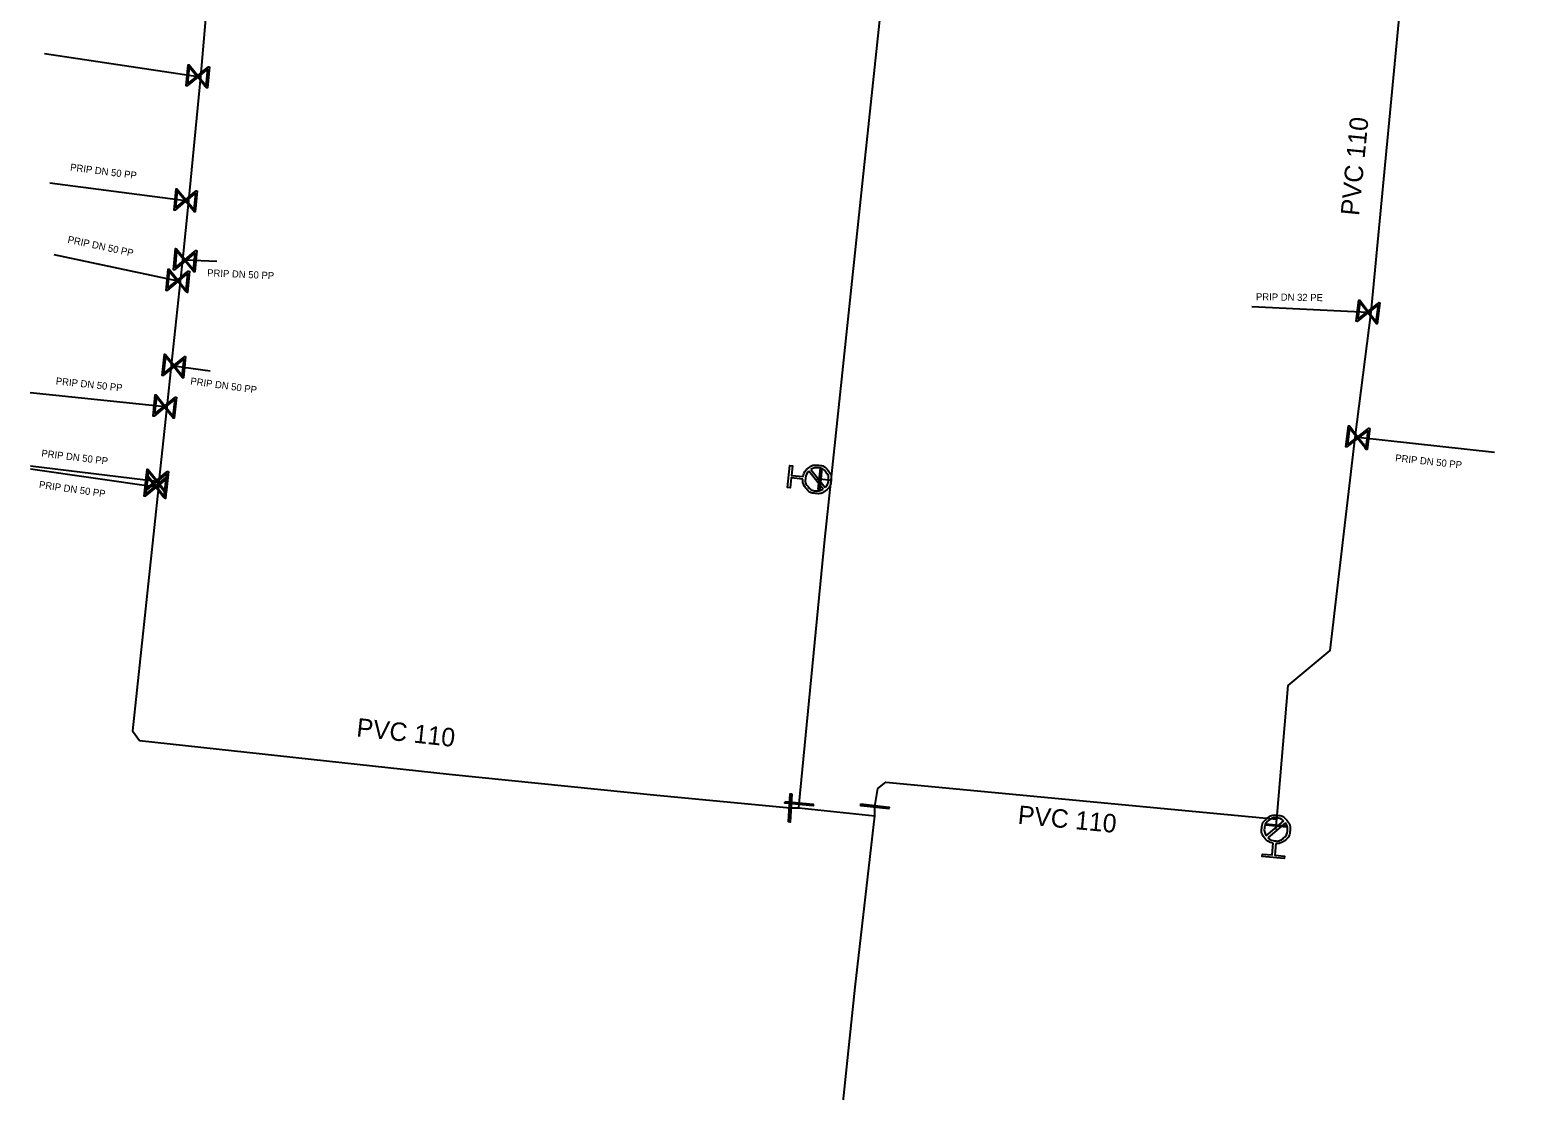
# Model space of a CAD drawing. Extents: x -643842 to -636370, y -1119190 to -1110210.
# Drawn here: x -642410.1 to -642303.8, y -1114138.7 to -1114063.9 of the extents above; entities that cross this region are included whole.
import ezdxf

# ---------------------------------------------------------------- set-up
doc = ezdxf.new("R2010")
doc.units = 0
for name, color, linetype in [('22', 7, 'Continuous'), ('Default', 7, 'Continuous'), ('Level 16', 7, 'Continuous'), ('Level 20', 7, 'Continuous'), ('Level 21', 7, 'Continuous'), ('Level 23', 7, 'Continuous'), ('Level 33', 7, 'Continuous')]:
    doc.layers.add(name, color=color, linetype=linetype)

msp = doc.modelspace()

# ---------------------------------------------------------------- linework, layer by layer
at = {"layer": 'Default'}
for points in [[(-642355.64, -1114095.39), (-642355.58, -1114095.03), (-642355.29, -1114094.8), (-642354.97, -1114094.54), (-642354.56, -1114094.59), (-642354.14, -1114094.63), (-642353.88, -1114094.95), (-642353.62, -1114095.27), (-642353.67, -1114095.69), (-642353.71, -1114096.1), (-642354.03, -1114096.36), (-642354.35, -1114096.62), (-642354.76, -1114096.58), (-642355.18, -1114096.53), (-642355.44, -1114096.21), (-642355.67, -1114095.93), (-642355.66, -1114095.57)], [(-642355.24, -1114095.01), (-642355.44, -1114095.21), (-642355.47, -1114095.5), (-642355.51, -1114095.83), (-642355.29, -1114096.09), (-642355.08, -1114096.36), (-642354.75, -1114096.39), (-642354.45, -1114096.42), (-642354.22, -1114096.27)], [(-642354.08, -1114096.15), (-642353.88, -1114095.95), (-642353.85, -1114095.67), (-642353.82, -1114095.33), (-642354.03, -1114095.07), (-642354.24, -1114094.81), (-642354.58, -1114094.77), (-642354.87, -1114094.74), (-642355.1, -1114094.89)], [(-642322.5, -1114121.23), (-642322.85, -1114121.17), (-642323.08, -1114120.89), (-642323.35, -1114120.57), (-642323.31, -1114120.15), (-642323.27, -1114119.74), (-642322.95, -1114119.48), (-642322.63, -1114119.22), (-642322.22, -1114119.25), (-642321.8, -1114119.29), (-642321.54, -1114119.61), (-642321.28, -1114119.93), (-642321.32, -1114120.34), (-642321.35, -1114120.76), (-642321.67, -1114121.02), (-642321.95, -1114121.26), (-642322.31, -1114121.25)], [(-642321.75, -1114119.66), (-642321.95, -1114119.47), (-642322.23, -1114119.44), (-642322.57, -1114119.41), (-642322.83, -1114119.63), (-642323.09, -1114119.84), (-642323.12, -1114120.18), (-642323.15, -1114120.46), (-642322.99, -1114120.7)], [(-642322.88, -1114120.84), (-642322.68, -1114121.03), (-642322.39, -1114121.06), (-642322.05, -1114121.09), (-642321.79, -1114120.88), (-642321.53, -1114120.66), (-642321.5, -1114120.33), (-642321.47, -1114120.04), (-642321.63, -1114119.8)]]:
    msp.add_open_spline(points, degree=3, dxfattribs=at)
at = {"layer": 'Level 16'}
for points in [[(-642397.49, -1114066.51), (-642397.63, -1114068), (-642397.7, -1114067.99), (-642397.78, -1114067.89), (-642398.31, -1114067.24), (-642399.06, -1114067.86), (-642399.13, -1114067.86), (-642398.98, -1114066.36), (-642398.92, -1114066.37), (-642398.3, -1114067.12), (-642397.65, -1114066.58), (-642397.56, -1114066.5), (-642397.49, -1114066.51)], [(-642399.02, -1114067.71), (-642398.37, -1114067.18), (-642398.91, -1114066.53), (-642399.02, -1114067.71)], [(-642397.6, -1114066.65), (-642398.25, -1114067.19), (-642397.71, -1114067.83), (-642397.6, -1114066.65)], [(-642398.34, -1114075.24), (-642398.48, -1114076.74), (-642398.55, -1114076.73), (-642398.63, -1114076.63), (-642399.16, -1114075.98), (-642399.91, -1114076.6), (-642399.98, -1114076.6), (-642399.84, -1114075.1), (-642399.77, -1114075.11), (-642399.15, -1114075.86), (-642398.51, -1114075.32), (-642398.41, -1114075.24), (-642398.34, -1114075.24)], [(-642399.87, -1114076.45), (-642399.22, -1114075.91), (-642399.76, -1114075.27), (-642399.87, -1114076.45)], [(-642398.45, -1114075.39), (-642399.1, -1114075.93), (-642398.56, -1114076.57), (-642398.45, -1114075.39)], [(-642398.38, -1114079.46), (-642398.52, -1114080.96), (-642398.59, -1114080.95), (-642398.67, -1114080.85), (-642399.2, -1114080.2), (-642399.95, -1114080.82), (-642400.02, -1114080.82), (-642399.88, -1114079.32), (-642399.81, -1114079.33), (-642399.19, -1114080.08), (-642398.55, -1114079.54), (-642398.45, -1114079.46), (-642398.38, -1114079.46)], [(-642399.91, -1114080.67), (-642399.26, -1114080.13), (-642399.8, -1114079.49), (-642399.91, -1114080.67)], [(-642398.49, -1114079.61), (-642399.14, -1114080.15), (-642398.6, -1114080.79), (-642398.49, -1114079.61)], [(-642398.9, -1114080.91), (-642399.04, -1114082.41), (-642399.11, -1114082.4), (-642399.19, -1114082.3), (-642399.72, -1114081.65), (-642400.47, -1114082.27), (-642400.54, -1114082.27), (-642400.4, -1114080.77), (-642400.33, -1114080.78), (-642399.71, -1114081.53), (-642399.07, -1114080.99), (-642398.97, -1114080.91), (-642398.9, -1114080.91)], [(-642400.43, -1114082.12), (-642399.78, -1114081.58), (-642400.32, -1114080.94), (-642400.43, -1114082.12)], [(-642399.01, -1114081.06), (-642399.66, -1114081.6), (-642399.12, -1114082.24), (-642399.01, -1114081.06)], [(-642314.98, -1114083.14), (-642315.17, -1114084.63), (-642315.23, -1114084.62), (-642315.31, -1114084.51), (-642315.83, -1114083.85), (-642316.59, -1114084.45), (-642316.66, -1114084.44), (-642316.47, -1114082.95), (-642316.4, -1114082.96), (-642315.81, -1114083.73), (-642315.15, -1114083.21), (-642315.05, -1114083.13), (-642314.98, -1114083.14)], [(-642316.54, -1114084.3), (-642315.88, -1114083.78), (-642316.4, -1114083.12), (-642316.54, -1114084.3)], [(-642315.09, -1114083.28), (-642315.76, -1114083.8), (-642315.24, -1114084.46), (-642315.09, -1114083.28)], [(-642399.16, -1114086.93), (-642399.32, -1114088.43), (-642399.39, -1114088.42), (-642399.47, -1114088.32), (-642400, -1114087.66), (-642400.75, -1114088.27), (-642400.81, -1114088.27), (-642400.66, -1114086.77), (-642400.59, -1114086.78), (-642399.98, -1114087.54), (-642399.33, -1114087.01), (-642399.23, -1114086.93), (-642399.16, -1114086.93)], [(-642400.71, -1114088.12), (-642400.05, -1114087.59), (-642400.58, -1114086.94), (-642400.71, -1114088.12)], [(-642399.27, -1114087.08), (-642399.93, -1114087.61), (-642399.4, -1114088.26), (-642399.27, -1114087.08)], [(-642399.8, -1114089.78), (-642399.96, -1114091.28), (-642400.03, -1114091.27), (-642400.11, -1114091.17), (-642400.64, -1114090.51), (-642401.39, -1114091.12), (-642401.45, -1114091.12), (-642401.3, -1114089.62), (-642401.23, -1114089.63), (-642400.62, -1114090.39), (-642399.97, -1114089.86), (-642399.87, -1114089.78), (-642399.8, -1114089.78)], [(-642401.35, -1114090.97), (-642400.69, -1114090.44), (-642401.22, -1114089.79), (-642401.35, -1114090.97)], [(-642399.91, -1114089.93), (-642400.57, -1114090.46), (-642400.04, -1114091.11), (-642399.91, -1114089.93)], [(-642315.7, -1114091.99), (-642315.89, -1114093.48), (-642315.96, -1114093.47), (-642316.03, -1114093.37), (-642316.55, -1114092.7), (-642317.31, -1114093.3), (-642317.38, -1114093.29), (-642317.19, -1114091.8), (-642317.12, -1114091.81), (-642316.53, -1114092.58), (-642315.87, -1114092.06), (-642315.77, -1114091.98), (-642315.7, -1114091.99)], [(-642317.27, -1114093.15), (-642316.6, -1114092.63), (-642317.12, -1114091.97), (-642317.27, -1114093.15)], [(-642315.81, -1114092.13), (-642316.48, -1114092.65), (-642315.96, -1114093.31), (-642315.81, -1114092.13)], [(-642400.43, -1114095.43), (-642400.59, -1114096.93), (-642400.66, -1114096.92), (-642400.74, -1114096.82), (-642401.27, -1114096.16), (-642402.02, -1114096.77), (-642402.08, -1114096.77), (-642401.93, -1114095.27), (-642401.86, -1114095.28), (-642401.25, -1114096.04), (-642400.6, -1114095.51), (-642400.5, -1114095.43), (-642400.43, -1114095.43)], [(-642400.38, -1114095.03), (-642400.54, -1114096.53), (-642400.61, -1114096.52), (-642400.69, -1114096.42), (-642401.22, -1114095.76), (-642401.97, -1114096.37), (-642402.03, -1114096.37), (-642401.88, -1114094.87), (-642401.81, -1114094.88), (-642401.2, -1114095.64), (-642400.55, -1114095.11), (-642400.45, -1114095.03), (-642400.38, -1114095.03)], [(-642401.93, -1114096.22), (-642401.27, -1114095.69), (-642401.8, -1114095.04), (-642401.93, -1114096.22)], [(-642400.49, -1114095.18), (-642401.15, -1114095.71), (-642400.62, -1114096.36), (-642400.49, -1114095.18)], [(-642354.31, -1114094.8), (-642354.47, -1114096.29), (-642354.57, -1114096.28), (-642354.41, -1114094.79), (-642354.31, -1114094.8)], [(-642401.98, -1114096.62), (-642401.32, -1114096.09), (-642401.85, -1114095.44), (-642401.98, -1114096.62)], [(-642400.54, -1114095.58), (-642401.2, -1114096.11), (-642400.67, -1114096.76), (-642400.54, -1114095.58)], [(-642356.91, -1114118.28), (-642354.92, -1114118.47), (-642354.93, -1114118.6), (-642356.92, -1114118.41), (-642356.91, -1114118.28)], [(-642356.43, -1114117.75), (-642356.55, -1114119.74), (-642356.67, -1114119.73), (-642356.55, -1114117.74), (-642356.43, -1114117.75)], [(-642351.57, -1114118.46), (-642349.58, -1114118.68), (-642349.59, -1114118.8), (-642351.58, -1114118.58), (-642351.57, -1114118.46)], [(-642323.04, -1114119.86), (-642321.55, -1114120), (-642321.56, -1114120.1), (-642323.05, -1114119.96), (-642323.04, -1114119.86)]]:
    msp.add_lwpolyline(points, dxfattribs=at)
at = {"layer": 'Level 21'}
for points in [[(-642355.93, -1114118.73), (-642355.92, -1114118.44), (-642354.11, -1114099.81), (-642353.66, -1114095.65), (-642351.42, -1114074.5), (-642339.32, -1113960.55), (-642339.3, -1113960.36)], [(-642350.59, -1114119.3), (-642350.58, -1114118.63), (-642350.38, -1114117.38), (-642349.8, -1114116.93), (-642322.25, -1114119.52), (-642321.46, -1114110.11), (-642318.48, -1114107.64), (-642316.72, -1114092.63), (-642315.6, -1114083.79), (-642313.37, -1114060.35), (-642311.96, -1114046.65), (-642310.13, -1114028.65), (-642309.98, -1114027.23), (-642308.29, -1114010.85), (-642306.82, -1113996.78), (-642306.38, -1113992.04), (-642304.52, -1113974.71), (-642303.9, -1113968.74), (-642303.85, -1113968.27), (-642308.05, -1113963.66), (-642339.07, -1113960.35), (-642339.3, -1113960.36)], [(-642397.62, -1114061.49), (-642398.11, -1114067.21), (-642398.95, -1114075.95), (-642399.39, -1114080.13), (-642399.54, -1114081.63), (-642400.17, -1114087.57), (-642400.48, -1114090.47), (-642401.04, -1114095.72), (-642401.08, -1114096.12), (-642402.91, -1114113.31), (-642402.42, -1114113.98), (-642380.59, -1114116.36), (-642365.96, -1114117.83), (-642356.55, -1114118.74), (-642355.93, -1114118.73)], [(-642355.93, -1114118.73), (-642350.59, -1114119.3)], [(-642356.89, -1114181.6), (-642356.88, -1114181.42), (-642356.64, -1114177.1), (-642355.35, -1114162.91), (-642354.48, -1114155.4), (-642351.98, -1114131.36), (-642350.59, -1114119.3)]]:
    msp.add_lwpolyline(points, dxfattribs=at)
at = {"layer": 'Level 23'}
for points in [[(-642409.1, -1114065.57), (-642398.31, -1114067.18), (-642398.11, -1114067.21)], [(-642408.73, -1114074.69), (-642399.16, -1114075.92), (-642398.95, -1114075.95)], [(-642408.44, -1114079.73), (-642399.72, -1114081.59), (-642399.54, -1114081.63)], [(-642396.97, -1114080.24), (-642399.2, -1114080.14), (-642399.39, -1114080.13)], [(-642324, -1114083.41), (-642315.82, -1114083.79), (-642315.6, -1114083.79)], [(-642397.44, -1114087.95), (-642399.99, -1114087.6), (-642400.17, -1114087.57)], [(-642410.12, -1114089.45), (-642400.63, -1114090.45), (-642400.48, -1114090.47)], [(-642306.9, -1114093.7), (-642316.54, -1114092.64), (-642316.72, -1114092.63)], [(-642410.1, -1114094.62), (-642401.21, -1114095.7), (-642401.04, -1114095.72)], [(-642410.09, -1114094.83), (-642401.26, -1114096.1), (-642401.08, -1114096.12)], [(-642354.66, -1114095.58), (-642354.44, -1114095.54), (-642353.66, -1114095.65)], [(-642322.31, -1114120.25), (-642322.3, -1114119.98), (-642322.25, -1114119.52)]]:
    msp.add_lwpolyline(points, dxfattribs=at)
at = {"layer": 'Level 33'}
for points in [[(-642355.66, -1114095.57), (-642356.48, -1114095.48), (-642356.55, -1114096.17), (-642356.73, -1114096.15), (-642356.57, -1114094.6), (-642356.39, -1114094.62), (-642356.46, -1114095.3), (-642355.64, -1114095.39)], [(-642354.22, -1114096.27), (-642355.24, -1114095.01)], [(-642355.1, -1114094.89), (-642354.08, -1114096.15)], [(-642322.99, -1114120.7), (-642321.75, -1114119.66)], [(-642321.63, -1114119.8), (-642322.88, -1114120.84)], [(-642322.31, -1114121.25), (-642322.39, -1114122.07), (-642321.7, -1114122.13), (-642321.72, -1114122.31), (-642323.28, -1114122.17), (-642323.26, -1114121.99), (-642322.57, -1114122.05), (-642322.5, -1114121.23)]]:
    msp.add_lwpolyline(points, dxfattribs=at)

# ---------------------------------------------------------------- texts
at = {"layer": '22'}
for s, rotation, p in [('PRIP DN 50 PP', 352.6783, (-642407.32, -1114073.82)), ('PRIP DN 50 PP', 347.9589, (-642407.51, -1114078.9)), ('PRIP DN 50 PP', 357.4394, (-642397.65, -1114081.27)), ('PRIP DN 32 PE', 359.1831, (-642323.72, -1114082.96)), ('PRIP DN 50 PP', 353.983, (-642408.33, -1114088.89)), ('PRIP DN 50 PP', 352.1899, (-642398.85, -1114088.89)), ('PRIP DN 50 PP', 353.0767, (-642409.35, -1114093.98)), ('PRIP DN 50 PP', 353.7815, (-642313.92, -1114094.31)), ('PRIP DN 50 PP', 351.8183, (-642409.52, -1114096.18))]:
    msp.add_text(s, height=0.5, rotation=rotation, dxfattribs=at).set_placement(p)
at = {"layer": 'Level 20'}
for rotation, p in [(84.3953, (-642316.46, -1114077.04)), (353.7779, (-642387.16, -1114113.69)), (354.6294, (-642340.54, -1114119.85))]:
    msp.add_text('PVC 110', height=1.3, rotation=rotation, dxfattribs=at).set_placement(p)

doc.saveas('drawing.dxf')
